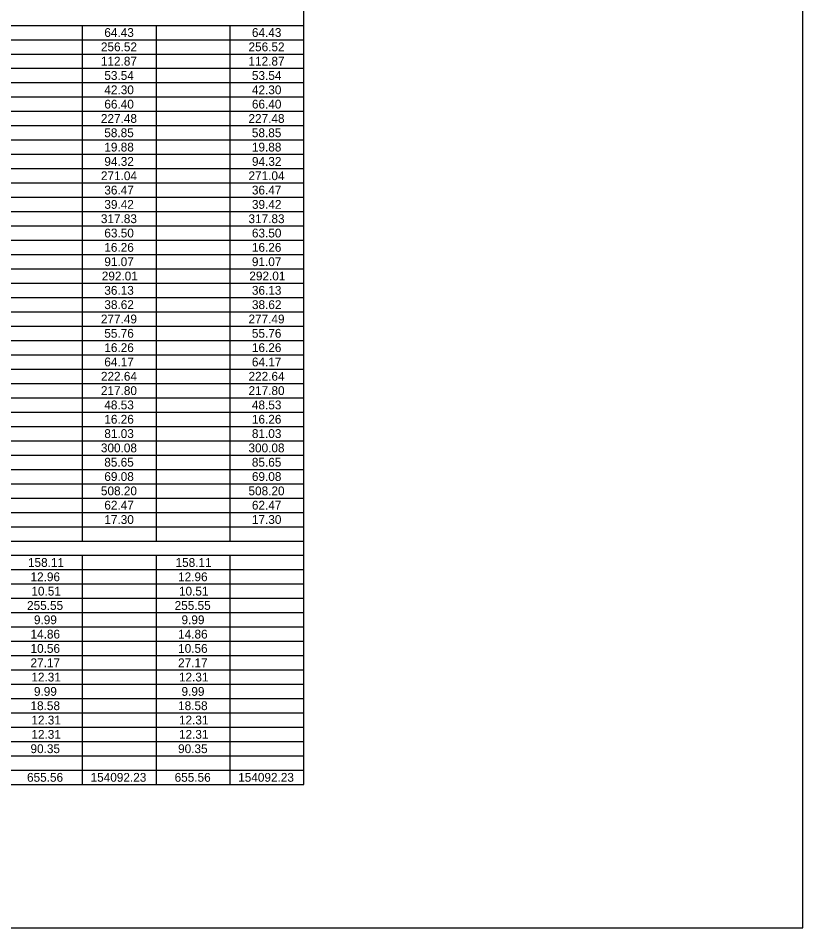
# Model space of a CAD drawing. Extents: x 2261867 to 2275370, y -3124789 to -3122260.
# Drawn here: x 2270239 to 2270720, y -3124789 to -3124232 of the extents above; entities that cross this region are included whole.
import ezdxf

# ---------------------------------------------------------------- set-up
doc = ezdxf.new("R2010")
doc.units = 0
doc.layers.add('Default', color=7, linetype='Continuous')
doc.layers.add('DSN_DRFT_Named-Boundary', color=7, linetype='Continuous')

msp = doc.modelspace()

# ---------------------------------------------------------------- linework, layer by layer
at = {"layer": 'Default'}
for p, q in [((2270414.11, -3124701.59), (2270414.11, -3123657.37)), ((2269400.16, -3124236.52), (2270414.11, -3124236.52)), ((2270278.54, -3124552.42), (2270278.54, -3124236.52)), ((2270278.54, -3124552.42), (2270278.54, -3124236.52)), ((2270323.73, -3124552.42), (2270323.73, -3124236.52)), ((2270323.73, -3124552.42), (2270323.73, -3124236.52)), ((2270368.92, -3124552.42), (2270368.92, -3124236.52)), ((2270368.92, -3124552.42), (2270368.92, -3124236.52)), ((2270414.11, -3124552.42), (2270414.11, -3124236.52)), ((2269400.16, -3124245.29), (2270414.11, -3124245.29)), ((2269400.16, -3124254.07), (2270414.11, -3124254.07)), ((2269400.16, -3124262.84), (2270414.11, -3124262.84)), ((2269400.16, -3124271.62), (2270414.11, -3124271.62)), ((2269400.16, -3124280.39), (2270414.11, -3124280.39)), ((2269400.16, -3124289.17), (2270414.11, -3124289.17)), ((2269400.16, -3124297.94), (2270414.11, -3124297.94)), ((2269400.16, -3124306.72), (2270414.11, -3124306.72)), ((2269400.16, -3124315.49), (2270414.11, -3124315.49)), ((2269400.16, -3124324.27), (2270414.11, -3124324.27)), ((2269400.16, -3124333.04), (2270414.11, -3124333.04)), ((2269400.16, -3124341.82), (2270414.11, -3124341.82)), ((2269400.16, -3124350.59), (2270414.11, -3124350.59)), ((2269400.16, -3124359.37), (2270414.11, -3124359.37)), ((2269400.16, -3124368.14), (2270414.11, -3124368.14)), ((2269400.16, -3124376.92), (2270414.11, -3124376.92)), ((2269400.16, -3124385.69), (2270414.11, -3124385.69)), ((2269400.16, -3124394.47), (2270414.11, -3124394.47)), ((2269400.16, -3124403.24), (2270414.11, -3124403.24)), ((2269400.16, -3124412.02), (2270414.11, -3124412.02)), ((2269400.16, -3124420.79), (2270414.11, -3124420.79)), ((2269400.16, -3124429.57), (2270414.11, -3124429.57)), ((2269400.16, -3124438.34), (2270414.11, -3124438.34)), ((2269400.16, -3124447.12), (2270414.11, -3124447.12)), ((2269400.16, -3124455.89), (2270414.11, -3124455.89)), ((2269400.16, -3124464.67), (2270414.11, -3124464.67)), ((2269400.16, -3124473.44), (2270414.11, -3124473.44)), ((2269400.16, -3124482.22), (2270414.11, -3124482.22)), ((2269400.16, -3124490.99), (2270414.11, -3124490.99)), ((2269400.16, -3124499.77), (2270414.11, -3124499.77)), ((2269400.16, -3124508.54), (2270414.11, -3124508.54)), ((2269400.16, -3124517.32), (2270414.11, -3124517.32)), ((2269400.16, -3124526.09), (2270414.11, -3124526.09)), ((2269400.16, -3124534.87), (2270414.11, -3124534.87)), ((2269400.16, -3124543.64), (2270414.11, -3124543.64)), ((2269400.16, -3124552.42), (2270414.11, -3124552.42)), ((2269400.16, -3124552.42), (2270414.11, -3124552.42)), ((2269400.16, -3124561.19), (2270414.11, -3124561.19)), ((2270278.54, -3124692.82), (2270278.54, -3124561.19)), ((2270278.54, -3124701.59), (2270278.54, -3124561.19)), ((2270323.73, -3124692.82), (2270323.73, -3124561.19)), ((2270323.73, -3124701.59), (2270323.73, -3124561.19)), ((2270368.92, -3124692.82), (2270368.92, -3124561.19)), ((2270368.92, -3124701.59), (2270368.92, -3124561.19)), ((2270414.11, -3124692.82), (2270414.11, -3124561.19)), ((2269400.16, -3124569.97), (2270414.11, -3124569.97)), ((2269400.16, -3124578.74), (2270414.11, -3124578.74)), ((2269400.16, -3124587.52), (2270414.11, -3124587.52)), ((2269400.16, -3124596.29), (2270414.11, -3124596.29)), ((2269400.16, -3124605.07), (2270414.11, -3124605.07)), ((2269400.16, -3124613.84), (2270414.11, -3124613.84)), ((2269400.16, -3124622.62), (2270414.11, -3124622.62)), ((2269400.16, -3124631.39), (2270414.11, -3124631.39)), ((2269400.16, -3124640.17), (2270414.11, -3124640.17)), ((2269400.16, -3124648.94), (2270414.11, -3124648.94)), ((2269400.16, -3124657.72), (2270414.11, -3124657.72)), ((2269400.16, -3124666.49), (2270414.11, -3124666.49)), ((2269400.16, -3124675.27), (2270414.11, -3124675.27)), ((2269400.16, -3124684.04), (2270414.11, -3124684.04)), ((2269400.16, -3124692.82), (2270414.11, -3124692.82)), ((2270046.44, -3124692.82), (2270414.11, -3124692.82)), ((2269400.16, -3124701.59), (2270414.11, -3124701.59))]:
    msp.add_line(p, q, dxfattribs=at)
at = {"layer": 'DSN_DRFT_Named-Boundary'}
msp.add_lwpolyline([(2269094.64, -3124789.38), (2270719.64, -3124789.38), (2270719.64, -3123623.23), (2269094.64, -3123623.23)], close=True, dxfattribs=at)

# ---------------------------------------------------------------- texts
at = {"layer": 'Default'}
for s, p in [('64.43', (2270291.87, -3124243.61)), ('64.43', (2270382.25, -3124243.61)), ('256.52', (2270289.8, -3124252.38)), ('256.52', (2270380.18, -3124252.38)), ('112.87', (2270289.77, -3124261.16)), ('112.87', (2270380.16, -3124261.16)), ('53.54', (2270291.88, -3124269.93)), ('53.54', (2270382.26, -3124269.93)), ('42.30', (2270291.88, -3124278.71)), ('42.30', (2270382.26, -3124278.71)), ('66.40', (2270291.88, -3124287.48)), ('66.40', (2270382.26, -3124287.48)), ('227.48', (2270289.77, -3124296.26)), ('227.48', (2270380.15, -3124296.26)), ('58.85', (2270291.85, -3124305.03)), ('58.85', (2270382.23, -3124305.03)), ('19.88', (2270291.87, -3124313.81)), ('19.88', (2270382.25, -3124313.81)), ('94.32', (2270291.9, -3124322.58)), ('94.32', (2270382.28, -3124322.58)), ('271.04', (2270289.79, -3124331.36)), ('271.04', (2270380.17, -3124331.36)), ('36.47', (2270291.87, -3124340.13)), ('36.47', (2270382.25, -3124340.13)), ('39.42', (2270291.9, -3124348.91)), ('39.42', (2270382.28, -3124348.91)), ('317.83', (2270289.77, -3124357.68)), ('317.83', (2270380.16, -3124357.68)), ('63.50', (2270291.88, -3124366.46)), ('63.50', (2270382.26, -3124366.46)), ('16.26', (2270291.87, -3124375.23)), ('16.26', (2270382.25, -3124375.23)), ('91.07', (2270291.87, -3124384.01)), ('91.07', (2270382.25, -3124384.01)), ('292.01', (2270290.3, -3124392.78)), ('292.01', (2270380.68, -3124392.78)), ('36.13', (2270291.87, -3124401.56)), ('36.13', (2270382.25, -3124401.56)), ('38.62', (2270291.9, -3124410.33)), ('38.62', (2270382.28, -3124410.33)), ('277.49', (2270289.77, -3124419.11)), ('277.49', (2270380.15, -3124419.11)), ('55.76', (2270291.87, -3124427.88)), ('55.76', (2270382.25, -3124427.88)), ('16.26', (2270291.87, -3124436.66)), ('16.26', (2270382.25, -3124436.66)), ('64.17', (2270291.87, -3124445.43)), ('64.17', (2270382.25, -3124445.43)), ('222.64', (2270289.79, -3124454.21)), ('222.64', (2270380.17, -3124454.21)), ('217.80', (2270289.78, -3124462.98)), ('217.80', (2270380.17, -3124462.98)), ('48.53', (2270291.87, -3124471.76)), ('48.53', (2270382.25, -3124471.76)), ('16.26', (2270291.87, -3124480.53)), ('16.26', (2270382.25, -3124480.53)), ('81.03', (2270291.87, -3124489.31)), ('81.03', (2270382.25, -3124489.31)), ('300.08', (2270289.77, -3124498.08)), ('300.08', (2270380.15, -3124498.08)), ('85.65', (2270291.85, -3124506.86)), ('85.65', (2270382.23, -3124506.86)), ('69.08', (2270291.87, -3124515.63)), ('69.08', (2270382.25, -3124515.63)), ('508.20', (2270289.78, -3124524.41)), ('508.20', (2270380.17, -3124524.41)), ('62.47', (2270291.87, -3124533.18)), ('62.47', (2270382.25, -3124533.18)), ('17.30', (2270291.88, -3124541.96)), ('17.30', (2270382.26, -3124541.96)), ('158.11', (2270245.1, -3124568.28)), ('158.11', (2270335.49, -3124568.28)), ('12.96', (2270246.68, -3124577.06)), ('12.96', (2270337.06, -3124577.06)), ('10.51', (2270247.2, -3124585.83)), ('10.51', (2270337.58, -3124585.83)), ('255.55', (2270244.56, -3124594.61)), ('255.55', (2270334.94, -3124594.61)), ('9.99', (2270248.77, -3124603.38)), ('9.99', (2270339.15, -3124603.38)), ('14.86', (2270246.68, -3124612.16)), ('14.86', (2270337.06, -3124612.16)), ('10.56', (2270246.68, -3124620.93)), ('10.56', (2270337.06, -3124620.93)), ('27.17', (2270246.68, -3124629.71)), ('27.17', (2270337.06, -3124629.71)), ('12.31', (2270247.2, -3124638.48)), ('12.31', (2270337.58, -3124638.48)), ('9.99', (2270248.77, -3124647.26)), ('9.99', (2270339.15, -3124647.26)), ('18.58', (2270246.67, -3124656.03)), ('18.58', (2270337.06, -3124656.03)), ('12.31', (2270247.2, -3124664.81)), ('12.31', (2270337.58, -3124664.81)), ('12.31', (2270247.2, -3124673.58)), ('12.31', (2270337.58, -3124673.58)), ('90.35', (2270246.66, -3124682.36)), ('90.35', (2270337.04, -3124682.36)), ('655.56', (2270244.54, -3124699.91)), ('154092.23', (2270283.47, -3124699.91)), ('655.56', (2270334.93, -3124699.91)), ('154092.23', (2270373.86, -3124699.91))]:
    msp.add_text(s, height=5.4, dxfattribs=at).set_placement(p)

doc.saveas('drawing.dxf')
